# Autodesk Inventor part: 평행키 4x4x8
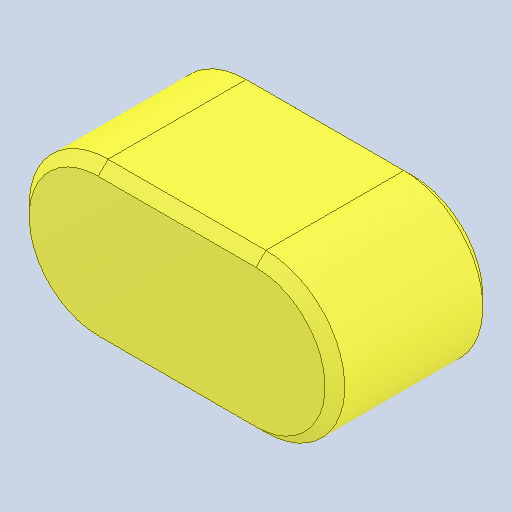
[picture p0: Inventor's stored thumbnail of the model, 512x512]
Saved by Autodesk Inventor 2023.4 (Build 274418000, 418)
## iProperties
Created: 2024-04
Part Number: 평행키 4x4x8
Material: 강철, 연강
Description: 평행 키
Document SubType Name: Modeling
Designer: EDU
Density: 7.85 g/cm^3
Appearance: 기본값
Author: jhkim
Sending System: Autodesk Inventor 2025
Preprocessor: ST-DEVELOPER v20
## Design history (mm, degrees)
node "평행키 4x4x81"
node "솔리드1"
body "Solid1"
